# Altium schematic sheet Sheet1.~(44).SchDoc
size A; SheetNumber: 1; SheetTotal: 1
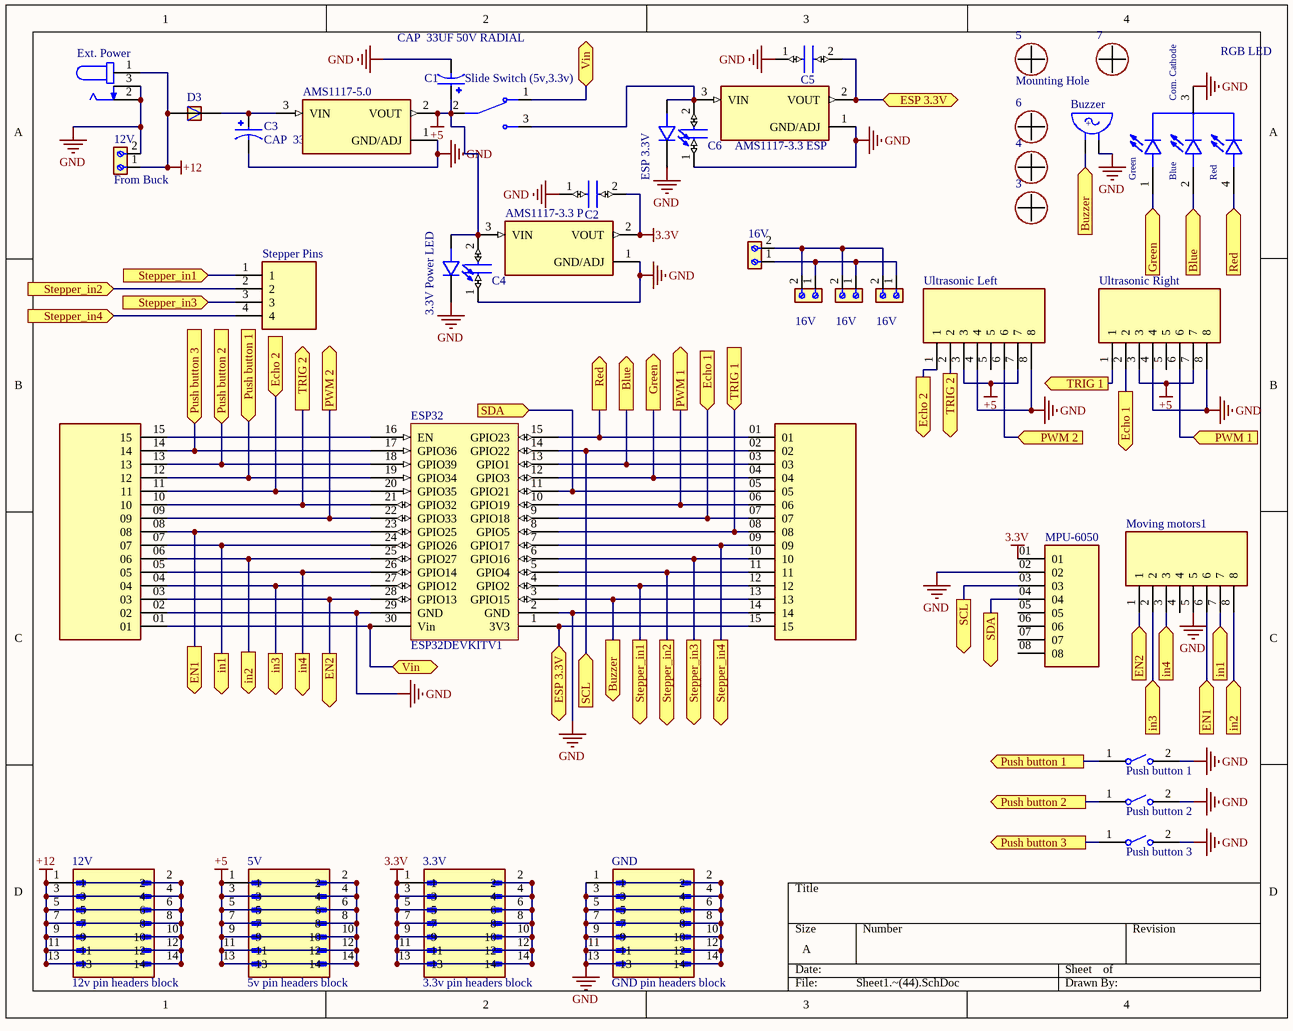
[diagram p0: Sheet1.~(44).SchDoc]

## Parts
(Parts that share a designator on the sheet are numbered #1, #2 ... from top to bottom, then left to right.)
3  Mounting Hole  [PCBComponent_1]  (value not drawn)
3.3V  3.3v pin headers block  [AMPHENOL_52601-S14-4LF]
3.3V_Power_LED  LED 5mm  [LED 5mm]  (value not drawn)
4  Mounting Hole  [PCBComponent_1]  (value not drawn)
5  Mounting Hole  [PCBComponent_1]
5V  5v pin headers block  [AMPHENOL_52601-S14-4LF]
6  Mounting Hole  [PCBComponent_1]  (value not drawn)
7  Mounting Hole  [PCBComponent_1]  (value not drawn)
12V#1  From Buck  [691213510002]
12V#2  12v pin headers block  [AMPHENOL_52601-S14-4LF]
16V#1  From Buck  [691213510002]  (value not drawn)
16V#2  From Buck  [691213510002]  (value not drawn)
16V#3  From Buck  [691213510002]  (value not drawn)
16V#4  From Buck  [691213510002]  (value not drawn)
AMS1117-3.3_ESP  AMS1117-3.3  [SOT229P700X180-4N]  (value not drawn)
AMS1117-3.3_P  AMS1117-3.3  [SOT229P700X180-4N]  (value not drawn)
AMS1117-5.0  AMS1117-5.0  [SOT229P700X180-4N]  (value not drawn)
Buzzer  Buzzer  [Buzzer 5V]  (value not drawn)
C1  CAP  33UF 50V RADIAL  [CAP  33UF 50V RADIAL]
C2  Ceramic Capacitor 100nF  [C320C]  (value not drawn)
C3  CAP  33UF 50V RADIAL  [CAP  33UF 50V RADIAL]
C4  Ceramic Capacitor 100nF  [C320C]  (value not drawn)
C5  Ceramic Capacitor 100nF  [C320C]  (value not drawn)
C6  Ceramic Capacitor 100nF  [C320C]  (value not drawn)
D3  RL207  [DIOAD1300W80L670D310]  (value not drawn)
ESP32  ESP32DEVKITV1  [ESP32DEVKITV1]
ESP_3.3V  LED 5mm  [LED 5mm]  (value not drawn)
Ext._Power  DC Power Jack Female Socket  [DC Power Jack Female Socket]  (value not drawn)
GND  GND pin headers block  [AMPHENOL_52601-S14-4LF]
J5  TS-115-T-A-1  [SAMTEC_TS-115-T-A-1]  (value not drawn)
J6  TS-115-T-A-1  [SAMTEC_TS-115-T-A-1]  (value not drawn)
Moving_motors1  Pin header female block 8 pin  [Pin header female block 8 pin]  (value not drawn)
MPU-6050  MPU-6050  [MPU-6050]  (value not drawn)
Push_button_1  FSM8JRT  [TE_FSM8JRT]  (value not drawn)
Push_button_2  FSM8JRT  [TE_FSM8JRT]  (value not drawn)
Push_button_3  FSM8JRT  [TE_FSM8JRT]  (value not drawn)
RGB_LED  common cathode  [LED RGB 5mm]  (value not drawn)
Slide_Switch_(5v,3.3v)  Slide Switch (5v,3.3v)  [Slide switch]  (value not drawn)
Stepper_Pins  Pin hreader 4 pins  [Pin hreader 4 pins]  (value not drawn)
Ultrasonic_Left  Pin header female block 8 pin  [Pin header female block 8 pin]  (value not drawn)
Ultrasonic_Right  Pin header female block 8 pin  [Pin header female block 8 pin]  (value not drawn)

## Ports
Blue (in, see Sheet1[2B]), Blue (out, see Sheet1[4B]), Buzzer (in, see Sheet1[2C]), Buzzer (out, see Sheet1[4A]), Echo 1 (in, see Sheet1[4B]), Echo 1 (out, see Sheet1[3B]), Echo 2 (in, see Sheet1[3B]), Echo 2 (out, see Sheet1[1B]), EN1 (in, see Sheet1[1C]), EN1 (out, see Sheet1[4C]), EN2 (in, see Sheet1[2C]), EN2 (out, see Sheet1[4C]), ESP 3.3V (bidir, see Sheet1[2C]), ESP 3.3V (bidir, see Sheet1[3A]), Green (in, see Sheet1[3B]), Green (out, see Sheet1[4B]), in1 (in, see Sheet1[1C]), in1 (out, see Sheet1[4C]), in2 (in, see Sheet1[1C]), in2 (out, see Sheet1[4C]), in3 (in, see Sheet1[1C]), in3 (out, see Sheet1[4C]), in4 (in, see Sheet1[1C]), in4 (out, see Sheet1[4C]), Push button 1 (in, see Sheet1[4C]), Push button 1 (out, see Sheet1[1B]), Push button 2 (in, see Sheet1[4D]), Push button 2 (out, see Sheet1[1B]), Push button 3 (in, see Sheet1[4D]), Push button 3 (out, see Sheet1[1B]), PWM 1 (in, see Sheet1[3B]), PWM 1 (out, see Sheet1[4B]), PWM 2 (in, see Sheet1[2B]), PWM 2 (out, see Sheet1[4B]), Red (in, see Sheet1[2B]), Red (out, see Sheet1[4B]), SCL (in, see Sheet1[3C]), SCL (out, see Sheet1[2C]), SDA (in, see Sheet1[4C]), SDA (out, see Sheet1[2B]), Stepper_in1 (in, see Sheet1[2C]), Stepper_in1 (out, see Sheet1[1B]), Stepper_in2 (in, see Sheet1[3C]), Stepper_in2 (out, see Sheet1[1B]), Stepper_in3 (in, see Sheet1[3C]), Stepper_in3 (out, see Sheet1[1B]), Stepper_in4 (in, see Sheet1[3C]), Stepper_in4 (out, see Sheet1[1B]), TRIG 1 (in, see Sheet1[4B]), TRIG 1 (out, see Sheet1[3B]), TRIG 2 (out, see Sheet1[1B]), TRIG 2 (out, see Sheet1[3B]), Vin (bidir, see Sheet1[2A]), Vin (bidir, see Sheet1[2C])

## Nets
3.3V: 3.3V.1 3.3V.2 3.3V.3 3.3V.4 3.3V.5 3.3V.6 3.3V.7 3.3V.8 3.3V.9 3.3V.10 3.3V.11 3.3V.12 3.3V.13 3.3V.14 AMS1117-3.3_P.2(VOUT) C2.2 MPU-6050.01
+5: 3.3V_Power_LED.A 5V.1 5V.2 5V.3 5V.4 5V.5 5V.6 5V.7 5V.8 5V.9 5V.10 5V.11 5V.12 5V.13 5V.14 AMS1117-3.3_P.3(VIN) AMS1117-5.0.2(VOUT) C1.P C4.2 Slide_Switch_(5v,3.3v).2 Ultrasonic_Left.3 Ultrasonic_Left.7 Ultrasonic_Right.3 Ultrasonic_Right.7
+12: 12V#1.1 12V#2.1 12V#2.2 12V#2.3 12V#2.4 12V#2.5 12V#2.6 12V#2.7 12V#2.8 12V#2.9 12V#2.10 12V#2.11 12V#2.12 12V#2.13 12V#2.14 D3.A Ext._Power.1
GND: 3.3V_Power_LED.C 12V#1.2 AMS1117-3.3_ESP.1(GND/ADJ) AMS1117-3.3_P.1(GND/ADJ) AMS1117-5.0.1(GND/ADJ) Buzzer.NEG C1.N C2.1 C3.N C4.1 C5.1 C6.1 ESP32.2(GND) ESP32.29(GND) ESP_3.3V.C Ext._Power.2 Ext._Power.3 GND.1 GND.2 GND.3 GND.4 GND.5 GND.6 GND.7 GND.8 GND.9 GND.10 GND.11 GND.12 GND.13 GND.14 J5.14 J6.02 Moving_motors1.5 MPU-6050.02 Push_button_1.2 Push_button_2.2 Push_button_3.2 RGB_LED.3(Com._Cathode) Ultrasonic_Left.4 Ultrasonic_Left.8 Ultrasonic_Right.4 Ultrasonic_Right.8
Blue: ESP32.13(GPIO1) J5.03 RGB_LED.2(BLUE) ; port Blue
Buzzer: Buzzer.POS ESP32.3(GPIO15) J5.13 ; port Buzzer
Echo 1: ESP32.9(GPIO18) J5.07 Ultrasonic_Right.2 ; port Echo 1
Echo 2: ESP32.20(GPIO35) J6.11 Ultrasonic_Left.1 ; port Echo 2
EN1: ESP32.23(GPIO25) J6.08 Moving_motors1.6 ; port EN1
EN2: ESP32.28(GPIO13) J6.03 Moving_motors1.1 ; port EN2
ESP 3.3V: AMS1117-3.3_ESP.2(VOUT) C5.2 ESP32.1(3V3) J5.15 ; port ESP 3.3V
Green: ESP32.12(GPIO3) J5.04 RGB_LED.1(Green) ; port Green
in1: ESP32.24(GPIO26) J6.07 Moving_motors1.7 ; port in1
in2: ESP32.25(GPIO27) J6.06 Moving_motors1.8 ; port in2
in3: ESP32.27(GPIO12) J6.04 Moving_motors1.2 ; port in3
in4: ESP32.26(GPIO14) J6.05 Moving_motors1.3 ; port in4
Push button 1: ESP32.19(GPIO34) J6.12 Push_button_1.1 ; port Push button 1
Push button 2: ESP32.18(GPIO39) J6.13 Push_button_2.1 ; port Push button 2
Push button 3: ESP32.17(GPIO36) J6.14 Push_button_3.1 ; port Push button 3
PWM 1: ESP32.10(GPIO19) J5.06 Ultrasonic_Right.6 ; port PWM 1
PWM 2: ESP32.22(GPIO33) J6.09 Ultrasonic_Left.6 ; port PWM 2
Red: ESP32.15(GPIO23) J5.01 RGB_LED.4(Red) ; port Red
SCL: ESP32.14(GPIO22) J5.02 MPU-6050.03 ; port SCL
SDA: ESP32.11(GPIO21) J5.05 MPU-6050.04 ; port SDA
Stepper_in1: ESP32.4(GPIO2) J5.12 Stepper_Pins.1 ; port Stepper_in1
Stepper_in2: ESP32.5(GPIO4) J5.11 Stepper_Pins.2 ; port Stepper_in2
Stepper_in3: ESP32.6(GPIO16) J5.10 Stepper_Pins.3 ; port Stepper_in3
Stepper_in4: ESP32.7(GPIO17) J5.09 Stepper_Pins.4 ; port Stepper_in4
TRIG 1: ESP32.8(GPIO5) J5.08 Ultrasonic_Right.1 ; port TRIG 1
TRIG 2: ESP32.21(GPIO32) J6.10 Ultrasonic_Left.2 ; port TRIG 2
Vin: ESP32.30(Vin) J6.01 Slide_Switch_(5v,3.3v).1 ; port Vin
Net16V#1_1: 16V#1.1 16V#2.1 16V#3.1 16V#4.1
Net16V#1_2: 16V#1.2 16V#2.2 16V#3.2 16V#4.2
NetAMS1117-3.3_ESP_3: AMS1117-3.3_ESP.3(VIN) C6.2 ESP_3.3V.A Slide_Switch_(5v,3.3v).3
NetAMS1117-5.0_3: AMS1117-5.0.3(VIN) C3.P D3.C
NetESP32_16: ESP32.16(EN) J6.15

Not connected (* = marked no-connect by the designer): Moving_motors1 4; MPU-6050 05 06 07 08; Ultrasonic_Left 5; Ultrasonic_Right 5

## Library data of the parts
3.3V 5V 12V#2 GND = 52601-S14-4LF: MF: {'manufacturer': u'Amphenol ICC (FCI)'}
3.3V_Power_LED ESP_3.3V = LED 5mm: Red 623nm LED Indication - Discrete 1.9V Radial; MF: {'manufacturer': u'Wurth Elektronik'}; MP: 151054RS03000
12V#1 16V#1-16V#4 = Terminal Block: 2 Position Wire to Board Terminal Block Horizontal with Board 0.200 (5.08mm) Through Hole; MF: Wurth Electronics
AMS1117-3.3_ESP AMS1117-3.3_P = AMS1117-3.3: MF: {'manufacturer': u'Advanced Monolithic Systems'}
AMS1117-5.0 = AMS1117-5.0: MF: {'manufacturer': u'Advanced Monolithic Systems'}
Buzzer = Buzzer 5V: BUZZER 2.3KHZ 4-6VDC; MF: {'manufacturer': u'Soberton Inc.'}; MP: WST-1205S
C1 C3 = CAP  33UF 50V RADIAL: NHG-A; MF: {'manufacturer': u'Panasonic'}; MP: ECA1HHG330I
C2 C4-C6 = Ceramic Capacitor 100nF: 0.1ÂµF Â±20% 50V Ceramic Capacitor Z5U Radial; MF: KEMET; MP: C320C104M5U5TA
D3 = RL207: Semiconductors and Actives, Power Diodes, Discretes (diodes, transistors, thyristors ...), Diodes; MF: {'manufacturer': u'Diodes Inc.'}
Ext._Power = DC Power Jack Female Socket: 2.0 mm Center Pin, 2.5 A, Right Angle, Through Hole, Dc Power Jack Connector; MF: {'manufacturer': u'CUI Devices'}; MP: PJ-002A
J5 J6 = TS-115-T-A-1: MF: {'manufacturer': u'Samtec'}
Moving_motors1 Ultrasonic_Left Ultrasonic_Right = Pin header female block 8 pin: MF: {'manufacturer': u'TE Connectivity'}; MP: 5-534998-4
Push_button_1-Push_button_3 = FSM8JRT: Tactile Switches PUSHBUTTON SWITCH TACT; MF: {'manufacturer': u'TE Connectivity'}
RGB_LED = LED RGB 5mm: MF: {'manufacturer': u'Kingbright'}; MP: WP154A4SUREQBFZGC
Slide_Switch_(5v,3.3v) = Slide switch: MF: {'manufacturer': u'E-Switch'}; MP: EG1206
Stepper_Pins = Pin hreader 4 pins: MF: {'manufacturer': u'TE Connectivity'}; MP: 2355181-4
